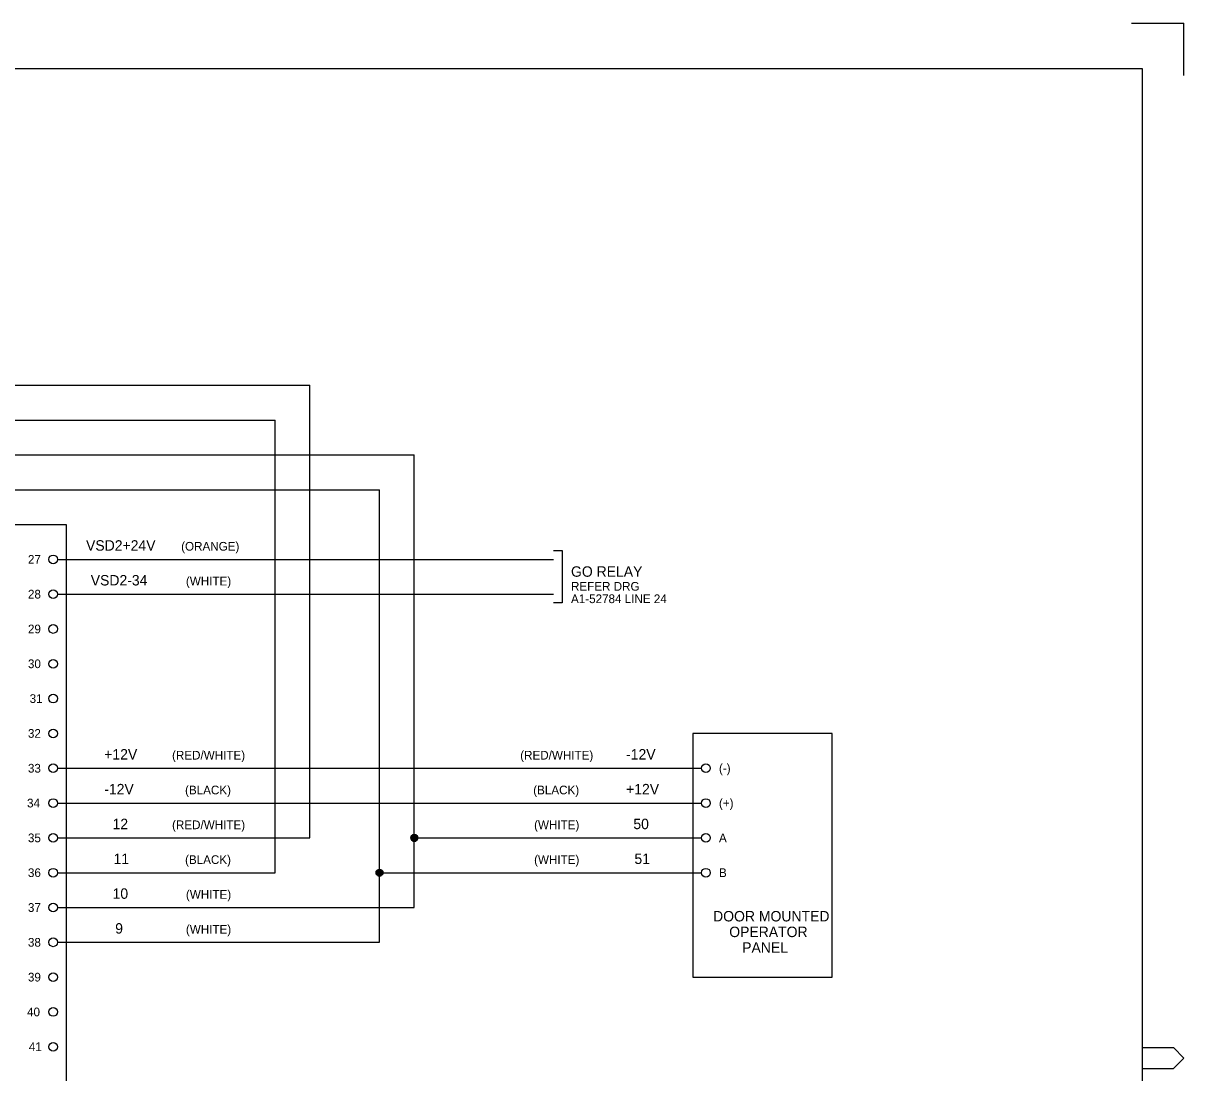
# Model space of a CAD drawing. Extents: x 0 to 841, y 0 to 594.
# Drawn here: x 507.7 to 841, y 292.5 to 594 of the extents above; entities that cross this region are included whole.
import ezdxf

# ---------------------------------------------------------------- set-up
doc = ezdxf.new("R2010")
doc.units = 0
for name, color, linetype in [('A1BORDER', 7, 'Continuous'), ('Level 1', 7, 'Continuous'), ('Level 10', 7, 'Continuous'), ('Level 5', 7, 'Continuous')]:
    doc.layers.add(name, color=color, linetype=linetype)

msp = doc.modelspace()

# ---------------------------------------------------------------- linework, layer by layer
at = {"layer": 'A1BORDER'}
for p, q in [((826, 594), (841, 594)), ((841, 579), (841, 594)), ((28, 581), (829, 581)), ((829, 581), (829, 15)), ((829, 299.76), (838, 299.76)), ((838, 299.76), (841, 296.76)), ((838, 293.76), (841, 296.76)), ((829, 293.76), (838, 293.76))]:
    msp.add_line(p, q, dxfattribs=at)
at = {"layer": 'Level 1'}
for p, q in [((227.5, 490), (590, 490)), ((590, 360), (590, 490)), ((227.5, 480), (580, 480)), ((580, 350), (580, 480)), ((227.5, 470), (620, 470)), ((620, 340), (620, 470)), ((227.5, 460), (610, 460)), ((610, 330), (610, 460)), ((517.5, 440), (660, 440)), ((517.5, 430), (660, 430)), ((517.5, 380), (702.5, 380)), ((517.5, 370), (702.5, 370)), ((517.5, 360), (590, 360)), ((620, 360), (702.5, 360)), ((517.5, 350), (580, 350)), ((610, 350), (702.5, 350)), ((517.5, 340), (620, 340)), ((517.5, 330), (610, 330))]:
    msp.add_line(p, q, dxfattribs=at)
for points in [[(320, 450), (520, 450), (520, 180), (320, 180)], [(740, 390), (700, 390), (700, 320), (740, 320)]]:
    msp.add_lwpolyline(points, close=True, dxfattribs=at)
msp.add_lwpolyline([(660, 442.5), (662.5, 442.5), (662.5, 427.5), (660, 427.5)], dxfattribs=at)
at = {"layer": 'Level 10'}
for p, q in [((619.05, 360.3), (620.95, 360.3)), ((619.2, 360.6), (620.8, 360.6)), ((619.56, 360.9), (620.44, 360.9)), ((620, 361), (620, 361)), ((619, 360), (620.99, 360)), ((619.05, 359.7), (620.95, 359.7)), ((619.2, 359.4), (620.8, 359.4)), ((619.56, 359.1), (620.44, 359.1)), ((609.05, 350.3), (610.95, 350.3)), ((609.2, 350.6), (610.8, 350.6)), ((609.56, 350.9), (610.44, 350.9)), ((610, 351), (610, 351)), ((609, 350), (610.99, 350)), ((609.05, 349.7), (610.95, 349.7)), ((609.2, 349.4), (610.8, 349.4)), ((609.56, 349.1), (610.44, 349.1))]:
    msp.add_line(p, q, dxfattribs=at)
for centre in [(620, 360), (610, 350)]:
    msp.add_circle(centre, 1, dxfattribs=at)
at = {"layer": 'Level 5'}
for centre in [(516.25, 440), (516.25, 430), (516.25, 420), (516.25, 410), (516.25, 400), (516.25, 390), (516.25, 380), (703.75, 380), (516.25, 370), (703.75, 370), (516.25, 360), (703.75, 360), (516.25, 350), (703.75, 350), (516.25, 340), (516.25, 330), (516.25, 320), (516.25, 310), (516.25, 300)]:
    msp.add_circle(centre, 1.25, dxfattribs=at)

# ---------------------------------------------------------------- texts
at = {"layer": 'Level 1'}
for s, height, p in [('27', 2.5, (509.02, 438.75)), ('GO RELAY', 3, (665, 435)), ('REFER DRG', 2.5, (665, 431)), ('28', 2.5, (509.02, 428.75)), ('A1-52784 LINE 24', 2.5, (665, 427.43)), ('29', 2.5, (509.02, 418.75)), ('30', 2.5, (509.02, 408.75)), ('31', 2.5, (509.51, 398.75)), ('32', 2.5, (509.02, 388.75)), ('33', 2.5, (509.02, 378.75)), ('(-)', 2.5, (707.5, 378.75)), ('34', 2.5, (508.77, 368.75)), ('(+)', 2.5, (707.5, 368.75)), ('35', 2.5, (509.02, 358.75)), ('A', 2.5, (707.5, 358.75)), ('36', 2.5, (509.02, 348.75)), ('B', 2.5, (707.5, 348.75)), ('37', 2.5, (509.02, 338.75)), ('38', 2.5, (509.02, 328.75)), ('39', 2.5, (509.02, 318.75)), ('40', 2.5, (508.77, 308.75)), ('41', 2.5, (509.27, 298.75))]:
    msp.add_text(s, height=height, dxfattribs=at).set_placement(p)
at = {"layer": 'Level 5'}
for s, height, p in [('VSD2+24V', 3, (525.71, 442.5)), ('(ORANGE)', 2.5, (553.03, 442.5)), ('VSD2-34', 3, (527.06, 432.5)), ('(WHITE)', 2.5, (554.4, 432.5)), ('+12V', 3, (530.94, 382.5)), ('(RED/WHITE)', 2.5, (550.41, 382.5)), ('(RED/WHITE)', 2.5, (650.41, 382.5)), ('-12V', 3, (680.82, 382.5)), ('-12V', 3, (530.94, 372.5)), ('(BLACK)', 2.5, (554.15, 372.5)), ('(BLACK)', 2.5, (654.15, 372.5)), ('+12V', 3, (680.82, 372.5)), ('12', 3, (533.33, 362.5)), ('(RED/WHITE)', 2.5, (550.41, 362.5)), ('(WHITE)', 2.5, (654.4, 362.5)), ('50', 3, (682.91, 362.5)), ('11', 3, (533.63, 352.5)), ('(BLACK)', 2.5, (554.15, 352.5)), ('(WHITE)', 2.5, (654.4, 352.5)), ('51', 3, (683.21, 352.5)), ('10', 3, (533.33, 342.5)), ('(WHITE)', 2.5, (554.4, 342.5)), ('DOOR MOUNTED', 3, (705.81, 336)), ('9', 3, (534.08, 332.5)), ('(WHITE)', 2.5, (554.4, 332.5)), ('OPERATOR', 3, (710.44, 331.5)), ('PANEL', 3, (714.17, 327))]:
    msp.add_text(s, height=height, dxfattribs=at).set_placement(p)

doc.saveas('drawing.dxf')
